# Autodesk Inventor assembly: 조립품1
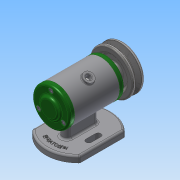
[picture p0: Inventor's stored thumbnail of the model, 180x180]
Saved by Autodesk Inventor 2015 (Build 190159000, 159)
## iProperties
Created: 2022-02
Part Number: 조립품1
Document SubType Name: Assembly
Designer: 학생용
Author: 학생용
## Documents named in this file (13)
- C:\Users\학생용\Desktop\720206V1030\조립품1.iam
- C:\Users\학생용\Desktop\720206V1030\본체.ipt
- C:\Users\학생용\Desktop\720206V1030\축.ipt
- C:\Users\학생용\Desktop\720206V1030\키 3 x 3 x 12.ipt
- C:\Users\학생용\Desktop\720206V1030\베어링 6002.ipt
- C:\Users\학생용\Desktop\720206V1030\앞커버.ipt
- C:\Users\학생용\Desktop\720206V1030\볼트 M4 x 10.ipt
- C:\Users\학생용\Desktop\720206V1030\오일 실 15 x 25 x 7.ipt
- C:\Users\학생용\Desktop\720206V1030\뒤커버.ipt
- C:\Users\학생용\Desktop\720206V1030\V벨트풀리.ipt
- C:\Users\학생용\Desktop\720206V1030\평와셔 8 x 17.ipt
- C:\Users\학생용\Desktop\720206V1030\스프링와셔 8.ipt
- C:\Users\학생용\Desktop\720206V1030\너트 M8.ipt
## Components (1 placed, 1 different names)
1. V벨트풀리:1
